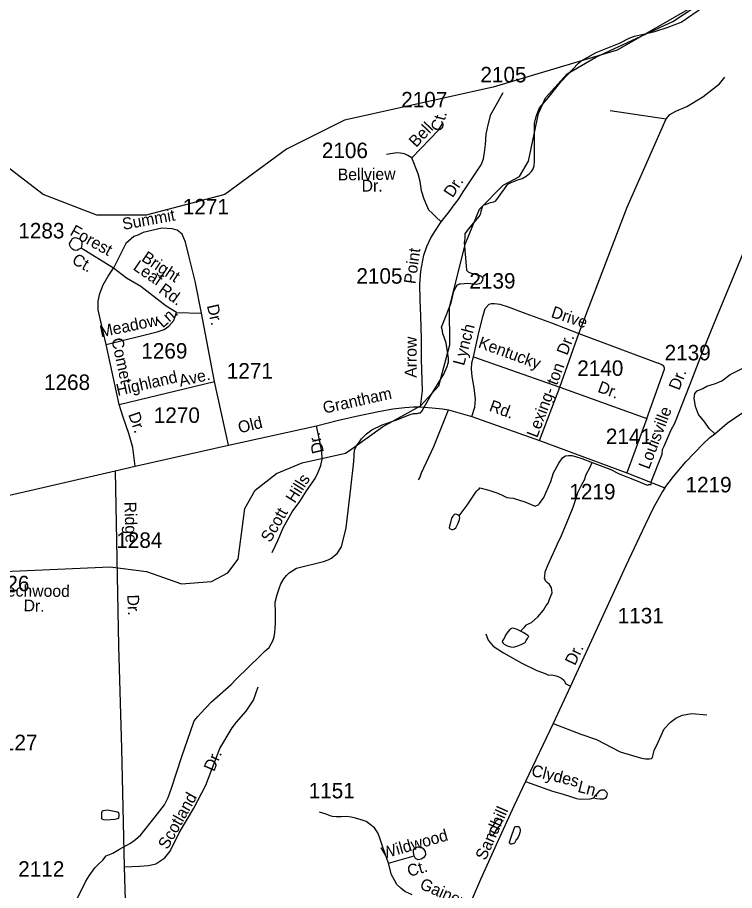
# Model space of a CAD drawing. Extents: x 2260773 to 2342389, y 552869 to 618546.
# Drawn here: x 2278661 to 2284444, y 575188 to 582228 of the extents above; entities that cross this region are included whole.
import ezdxf

# ---------------------------------------------------------------- set-up
doc = ezdxf.new("R2010")
doc.units = 0
for name, color, linetype in [('Exist Boundary Political Urban Extension UEB', 7, 'Continuous'), ('Exist Hydrographic Misc Water Feature', 7, 'Continuous'), ('Exist Road Non-System Type 51', 7, 'Continuous'), ('Exist Road Non-System Type 51 Label', 7, 'Continuous'), ('Exist Road Secondary Type 51 Attributed', 7, 'Continuous'), ('Exist Road Secondary Type 51 Label', 7, 'Continuous'), ('Exist Road Secondary Type 51 Number Label', 7, 'Continuous')]:
    doc.layers.add(name, color=color, linetype=linetype)

msp = doc.modelspace()

# ---------------------------------------------------------------- linework, layer by layer
at = {"layer": 'Exist Boundary Political Urban Extension UEB'}
msp.add_lwpolyline([(2284196, 582364.4), (2283496.6, 581964.8), (2282497.4, 581665.1), (2281298.4, 581398.7), (2280832.1, 581165.6), (2280332.5, 580799.2), (2279699.7, 580632.7), (2279300, 580632.7), (2278867.1, 580799.2), (2278567.3, 581032.4), (2278267.6, 581432), (2278167.6, 581931.5), (2278101, 582497.6)], dxfattribs=at)
at = {"layer": 'Exist Hydrographic Misc Water Feature'}
for points in [[(2278251.7, 577746.1), (2279408.8, 577798.2), (2279700.8, 577759.5), (2279984.8, 577661.9), (2280225.7, 577680), (2280358.8, 577749.4), (2280440.8, 577859.3), (2280494.7, 578268.1), (2280576.8, 578417.3), (2280750.6, 578551.6), (2280957.7, 578635.9), (2281307.8, 578714.1), (2281356.8, 578749.2), (2281604.7, 578927.9), (2281911.9, 579095.5), (2282059.7, 579256.4), (2282148.7, 579589.1), (2282145.8, 579890.9), (2282273.8, 580406.5), (2282387.8, 580682.9), (2282577.9, 580875.8), (2282710.7, 580945.4), (2282783.7, 581068.5), (2282863.7, 581453.9), (2282920.7, 581580.6), (2283093.8, 581773.9), (2283325.7, 581907), (2283947.8, 582196.1), (2284229.8, 582383.8)], [(2281393.5, 578768.1), (2281393.3, 578771.8), (2281413, 578798.1), (2281436.5, 578830.6), (2281476.3, 578870.8), (2281520, 578903.1), (2281601.2, 578944.1), (2281721.2, 578984.8), (2281834.6, 579030.2), (2281848.5, 579032.1), (2281856.3, 579034.2), (2281868.8, 579034.3), (2281884.4, 579034.4), (2281900.4, 579040.5), (2281910.6, 579040.6), (2281924.4, 579056.8), (2281989.4, 579171.5), (2282099.3, 579352.4), (2282126.8, 579414.8), (2282136.6, 579450.6), (2282138.2, 579480.8), (2282119, 579602.5), (2282102.6, 579650.4), (2282090.7, 579678.1), (2282088.2, 579702), (2282080.2, 579730), (2282095.8, 579770.2), (2282157.9, 579926.7), (2282181.3, 580020.5), (2282198.9, 580054.8), (2282210.8, 580070.8), (2282226.6, 580079), (2282234.6, 580081), (2282294.5, 580085.8), (2282362.6, 580076.3), (2282386.6, 580082.5), (2282402.3, 580090.6), (2282408.3, 580102.7), (2282414.2, 580110.7), (2282416.1, 580124.6), (2282406.2, 580138.7), (2282385.9, 580146.6), (2282323.8, 580162.1), (2282299.4, 580173.9), (2282285.7, 580187.7), (2282285.3, 580193.4), (2282283.4, 580225.4), (2282265.8, 580413.4), (2282271.1, 580445.4), (2282270.5, 580483.2), (2282298.8, 580519.5), (2282385.1, 580622.5), (2282399.3, 580646.2), (2282401.3, 580668.3), (2282414.2, 580708.5), (2282422.4, 580716.6), (2282436.8, 580720.5), (2282476.6, 580735.2), (2282502.2, 580741.4), (2282520.2, 580749.3), (2282541.8, 580779.7), (2282616.6, 580882.4), (2282642.9, 580896.7), (2282688.4, 580915), (2282730.4, 580929.3), (2282764.1, 580947.8), (2282791.9, 580969.9), (2282805.7, 580986.1), (2282819.4, 581008), (2282829.3, 581030.4), (2282831.3, 581068.2), (2282830.1, 581372.1), (2282843.6, 581428.1), (2282857.1, 581464.1), (2282870.5, 581498.2), (2282930.4, 581567.1), (2283046.8, 581710.1), (2283185.2, 581859.2), (2283207.4, 581877.4), (2283328.6, 581944.3), (2283515.6, 582020.3), (2283595.3, 582061), (2283637, 582075.5), (2283687, 582087.8), (2283802.4, 582115), (2283900.2, 582145.7), (2284014.1, 582188.5), (2284194.3, 582312.2)], [(2283295.3, 578640.2), (2283446.3, 578583.4), (2283514.3, 578548), (2283650.5, 578493.4), (2283734.8, 578458.4), (2283745, 578456.4), (2283748.7, 578462.4), (2283770.7, 578462.3), (2283772.9, 578482.7), (2283860.5, 578707.1), (2283864.2, 578745.1), (2283876.1, 578771.2), (2283932.6, 578901.8), (2283962.2, 578955.8), (2284087.3, 579271.1), (2284194.5, 579549.8), (2284301.5, 579812.7), (2284421.1, 580099.6), (2284514.8, 580328.4)], [(2279134.8, 575106.7), (2279213.6, 575263.6), (2279238.8, 575307.6), (2279284.5, 575372.1), (2279320, 575406.5), (2279349.7, 575434.5), (2279375.6, 575467.1), (2279429.3, 575489.4), (2279484.9, 575521.9), (2279572, 575570.5), (2279614, 575601), (2279655.9, 575637.3), (2279772.1, 575782.4), (2279847, 575879), (2279876.7, 575937.4), (2279903.8, 576013.6), (2279987.2, 576270.3), (2280080.7, 576540.9), (2280086.5, 576557), (2280101, 576575.1), (2280114.8, 576591.3), (2280136.1, 576615.3), (2280225.5, 576710.1), (2280383.8, 576849.7), (2280421.5, 576889.8), (2280459.5, 576928.3), (2280490.8, 576956.4), (2280534.3, 577000.9), (2280610, 577071.5), (2280659.2, 577120), (2280691.2, 577148.5), (2280707, 577176.5), (2280720.5, 577202.4), (2280732, 577232.7), (2280735.9, 577268.6), (2280741, 577342.9), (2280742.4, 577430.7), (2280739.8, 577514.6), (2280756.8, 577576.5), (2280770.5, 577622.7), (2280784.1, 577660.8), (2280809.5, 577701.2), (2280831.6, 577729.5), (2280853.2, 577749.4), (2280881.1, 577767.9), (2280910.8, 577788.1), (2281128.6, 577840.1), (2281167.7, 577854.4), (2281194, 577868.7), (2281215.7, 577887), (2281239.5, 577904.8), (2281275, 577959.5), (2281311.5, 578111.8), (2281350.2, 578432), (2281372.6, 578648), (2281379.7, 578741.8), (2281391.2, 578760), (2281393.5, 578768.1)], [(2282224.2, 578209.9), (2282287.1, 578294.9), (2282364, 578407.4), (2282371.8, 578415.5), (2282384.1, 578427.5), (2282390, 578435.5), (2282399.9, 578433.6), (2282462, 578416.1), (2282536.4, 578392.8), (2282574.4, 578373.3), (2282608.6, 578357.6), (2282630.6, 578353.9), (2282658.5, 578352.1), (2282753, 578322.8), (2282837.3, 578287.8), (2282847.1, 578294), (2282859, 578295.9), (2282870.7, 578310), (2282906.6, 578356.5), (2282963, 578487.1), (2282984.5, 578557.2), (2283027.8, 578633.4), (2283057.3, 578677.7), (2283067.5, 578685.8), (2283081.3, 578693.9), (2283104.8, 578696), (2283131.1, 578694.6), (2283161.2, 578686.8), (2283213.5, 578671.2), (2283295.3, 578640.2)], [(2282718.7, 577279.3), (2282726.3, 577287.5), (2282750.3, 577311.5), (2282767.7, 577331.9), (2282782.3, 577339.9), (2282805.7, 577350.2), (2282857.8, 577394.6), (2282904.5, 577448.8), (2282924.6, 577485.2), (2282940.2, 577505.1), (2282949.8, 577529.2), (2282965.8, 577569.3), (2282973.4, 577589.7), (2282971.2, 577609.5), (2282967.1, 577629.6), (2282961.1, 577643.5), (2282951.3, 577655.1), (2282933, 577673.2), (2282918.3, 577686.8), (2282918.5, 577692.9), (2282910.7, 577707), (2282914.6, 577720.7), (2282918, 577757), (2282941.6, 577817.1), (2283008.1, 577963.6), (2283025.5, 578001.6), (2283041.1, 578032.1), (2283088.2, 578148.2), (2283143, 578278.7), (2283168, 578352.8), (2283179.7, 578396.9), (2283213.3, 578461.1), (2283235.1, 578499.2), (2283248.4, 578541.8), (2283276.1, 578595.6), (2283295.3, 578640.2)], [(2282224.2, 578209.9), (2282215.7, 578216), (2282204.1, 578219.8), (2282189.9, 578222), (2282182.1, 578217.9), (2282172.3, 578207.6), (2282162, 578189.7), (2282150.9, 578145.5), (2282145, 578125.3), (2282143.2, 578111.4), (2282145, 578107.4), (2282149.5, 578103.5), (2282165.3, 578099.5), (2282173.5, 578099.5), (2282184.8, 578103.9), (2282197.1, 578111.7), (2282214.5, 578150.1), (2282226.4, 578180), (2282228.5, 578192.2), (2282226.2, 578204.3), (2282224.2, 578209.9)], [(2282718.7, 577279.3), (2282690.2, 577292.9), (2282666.7, 577301), (2282656.2, 577304.6), (2282646.6, 577300.8), (2282634.5, 577296.5), (2282615, 577274.3), (2282597.1, 577246.2), (2282585, 577220), (2282573.6, 577203.9), (2282571.5, 577194), (2282577.5, 577183.8), (2282585.5, 577176.1), (2282611.7, 577162.5), (2282639.8, 577152.5), (2282661.5, 577150.9), (2282695.6, 577161.2), (2282723.5, 577173.2), (2282755.2, 577187.8), (2282765.1, 577203.8), (2282775.1, 577219.8), (2282780.9, 577231.9), (2282784.8, 577237.7), (2282776.8, 577245.8), (2282740.5, 577267.5), (2282718.7, 577279.3)], [(2279340.5, 575796.3), (2279340.5, 575818.2), (2279345.8, 575830.4), (2279354.2, 575834.4), (2279386, 575839), (2279468, 575821.7), (2279475.8, 575817.7), (2279478.5, 575799.5), (2279476.5, 575769.8), (2279466.4, 575767.6), (2279446.5, 575761.3), (2279412.7, 575757.1), (2279374.7, 575756.7), (2279356.9, 575758.6), (2279344.8, 575762.5), (2279340.7, 575766.3), (2279340.5, 575772.4), (2279340.7, 575776.5), (2279340.5, 575796.3)], [(2282513.1, 575738.1), (2282478, 575687.8), (2282471.6, 575665.7), (2282470.2, 575653.7), (2282470.2, 575644), (2282473.9, 575637.7), (2282480.1, 575631.9), (2282492.6, 575632.1), (2282505.9, 575646.3), (2282523.5, 575678.5), (2282557.6, 575716.8), (2282559.2, 575726.7), (2282567.2, 575738.9), (2282567.2, 575748.6), (2282567.2, 575758.7), (2282552.8, 575762.5), (2282543.2, 575760.3), (2282531.1, 575756.5), (2282523.1, 575754.4), (2282513.1, 575738.1)], [(2282708.1, 575638.2), (2282700.1, 575618.3), (2282688, 575603.9), (2282684.3, 575600), (2282680.4, 575592), (2282670.8, 575571.6), (2282660.7, 575567.8), (2282652.7, 575565.8), (2282644.7, 575563.4), (2282636.5, 575563.4), (2282636.9, 575567.4), (2282628.5, 575571.5), (2282628.3, 575577.6), (2282645.9, 575627.6), (2282667.5, 575689.7), (2282671.6, 575701.7), (2282681.2, 575705.9), (2282691.5, 575703.9), (2282701.3, 575704.1), (2282709.3, 575693.9), (2282715.5, 575684.1), (2282715.9, 575666.2), (2282713.6, 575656), (2282708.1, 575638.2)]]:
    msp.add_lwpolyline(points, dxfattribs=at)
at = {"layer": 'Exist Road Non-System Type 51'}
for p, q in [((2283440.7, 581477.8), (2283893.2, 581410.1)), ((2283736.9, 578993.8), (2283574.3, 578557.4)), ((2281653.5, 575407.9), (2281860.5, 575469.5))]:
    msp.add_line(p, q, dxfattribs=at)
for points in [[(2283893.2, 581410.1), (2283922.9, 581444.4), (2283970.6, 581470.9), (2284060.1, 581509.6), (2284189.2, 581586.8), (2284322.3, 581692.1), (2284365.8, 581746.4)], [(2283187.9, 579678.6), (2283578, 580697.7), (2283893.2, 581410.1)], [(2279173.6, 580368.3), (2279153.8, 580356.1), (2279139.8, 580350), (2279119.7, 580351.8), (2279105.7, 580359.7), (2279091.5, 580371.6), (2279083.5, 580389.5), (2279081.2, 580405.4), (2279093, 580425.5), (2279104.8, 580445.7), (2279124.7, 580453.9), (2279140.7, 580452), (2279162.9, 580440.3), (2279179, 580418.4), (2279179.2, 580400.4), (2279173.6, 580368.3)], [(2283879, 579399.8), (2283874.2, 579415), (2283868.1, 579419.6), (2283859, 579427.2), (2283828.5, 579439.4)], [(2284285.9, 578871.8), (2284240.7, 578913.4), (2284204.6, 578964), (2284154, 579027.2), (2284128.7, 579090.4), (2284119.7, 579159.1), (2284125.1, 579195.2), (2284144.1, 579216), (2284187.4, 579235.9), (2284221.8, 579254), (2284290.4, 579277.5), (2284342.7, 579299.1), (2284409.6, 579347.9), (2284526.9, 579409.4), (2284590.2, 579418.4)], [(2283736.9, 578993.8), (2283854.3, 579323.5), (2283879.5, 579393.1), (2283879, 579399.8)], [(2281894.7, 578500.8), (2281907.4, 578515.2), (2281920, 578555), (2282019.4, 578768.2), (2282136.7, 579064.5)], [(2280715.5, 577913.5), (2280764.3, 578014.7), (2280804, 578112.3), (2280876.2, 578240.6), (2280937.6, 578323.7), (2280991.8, 578410.4), (2281062.2, 578511.6), (2281087.5, 578560.4), (2281107.4, 578614.6), (2281118.2, 578667), (2281114.6, 578728.5), (2281100.2, 578809.8), (2281073.1, 578934.4)], [(2282437.5, 577257.3), (2282457.4, 577206.7), (2282498.9, 577159.8), (2282580.2, 577105.6), (2282730.1, 577022.4), (2282851.1, 576962.8), (2282916.1, 576937.5), (2282945, 576924.9), (2282970.3, 576926.7), (2283004.6, 576919.5), (2283028.1, 576912.2), (2283049.7, 576901.4), (2283067.8, 576885.1), (2283084, 576856.2), (2283121.1, 576835.4)], [(2279521.8, 575378.5), (2279644.6, 575385.7), (2279718.6, 575389.3), (2279778.2, 575403.8), (2279849.5, 575451.3), (2279893.8, 575505), (2279966.1, 575653.1), (2280083.4, 575851.9), (2280179.2, 576038), (2280253.2, 576229.5), (2280292.9, 576333.4), (2280392.2, 576501.5), (2280428.4, 576544.8), (2280506, 576634.3), (2280563.8, 576723.7), (2280601.7, 576832.1)], [(2282982, 576535.6), (2283205.9, 576448.2), (2283332.2, 576407), (2283521.5, 576307.1), (2283694.2, 576256.7), (2283727.1, 576250.3), (2283745.6, 576249.5), (2283759.2, 576250.3), (2283775.3, 576252.7), (2283782.5, 576260.7), (2283785.6, 576273.5), (2283796.8, 576318.3), (2283828.2, 576385.5), (2283877.4, 576490.8), (2283928.9, 576544.6), (2283971.4, 576578.1), (2284020.7, 576602.8), (2284099, 576616.2), (2284222.1, 576605)], [(2282759.3, 576068.6), (2282976.4, 575990.2), (2283054.8, 575967.8), (2283128.6, 575943.2), (2283168.9, 575929.7), (2283200.3, 575925.3), (2283280.9, 575927.5), (2283310, 575936.5)], [(2283310, 575936.5), (2283331.7, 575930.9), (2283358.2, 575928.2), (2283376.6, 575926.8), (2283390, 575929.1), (2283401.2, 575933.6), (2283408.9, 575939), (2283415.6, 575947), (2283417.4, 575957.8), (2283418.7, 575968.6), (2283414.7, 575978.4), (2283404.8, 575990.6), (2283395, 575996.4), (2283383.7, 575997.3), (2283372.1, 575996.8), (2283362.2, 575993.7), (2283351, 575985.6), (2283333.5, 575968.6), (2283320.1, 575954.7), (2283312.9, 575944.3), (2283310, 575936.5)], [(2281860.5, 575469.5), (2281854.3, 575495.5), (2281856.3, 575515.4), (2281868, 575531.6), (2281891.9, 575539.7), (2281913.9, 575540), (2281934.1, 575528.2), (2281950.2, 575502.3), (2281952.4, 575476.3), (2281938.8, 575454.2), (2281916.8, 575442), (2281892.9, 575435.9), (2281870.9, 575447.5), (2281860.5, 575469.5)]]:
    msp.add_lwpolyline(points, dxfattribs=at)
at = {"layer": 'Exist Road Secondary Type 51 Attributed'}
for p, q in [((2279435.1, 580207.5), (2279173.6, 580368.3)), ((2279944.4, 579849.6), (2280144.8, 579842.4)), ((2280249.6, 579291.3), (2280144.8, 579842.4)), ((2279482.1, 579107), (2279375.1, 579590.9)), ((2282339.1, 579490.7), (2283034.4, 579247.6)), ((2279482.1, 579107), (2280249.6, 579291.3)), ((2280363.4, 578780), (2280249.6, 579291.3)), ((2282870, 578817.6), (2283034.4, 579247.6)), ((2283034.4, 579247.6), (2283736.9, 578993.8)), ((2282324.7, 579010.9), (2282870, 578817.6)), ((2279609.3, 578610.6), (2280363.4, 578780)), ((2279450.1, 578573.1), (2279609.3, 578610.6))]:
    msp.add_line(p, q, dxfattribs=at)
for points in [[(2282079.1, 580579.3), (2282133.2, 580648), (2282158.5, 580682.3), (2282174.8, 580705.8), (2282216.3, 580756.4), (2282261.5, 580829.1), (2282400.5, 581040.1), (2282418.6, 581087.1), (2282427.6, 581139.5), (2282434.8, 581204.5), (2282442, 581287.6), (2282456.5, 581361.7), (2282478.2, 581444.8), (2282525.1, 581526.1), (2282579.3, 581621.9)], [(2281842.5, 581096.1), (2281987, 581247), (2282055.6, 581318.3), (2282093.5, 581381.6)], [(2281842.5, 581096.1), (2281810, 581116), (2281782.9, 581126.8), (2281750.4, 581132.2), (2281721.5, 581135.8), (2281638.4, 581123.2)], [(2282079.1, 580579.3), (2282035.7, 580619.1), (2282003.2, 580651.6), (2281979.7, 580673.3), (2281961.7, 580711.2), (2281941.8, 580763.6), (2281920.1, 580830.5), (2281909.3, 580904.6), (2281893.1, 580967.8), (2281842.5, 581096.1)], [(2281911, 579088), (2281928.8, 579216.8), (2281920.1, 579471.7), (2281918.3, 579639.7), (2281912.9, 579820.4), (2281909.3, 579951.4), (2281907.5, 580077.9), (2281914.7, 580180.9), (2281938.2, 580311), (2281961.7, 580379.7), (2281996, 580450.1), (2282032.1, 580509.8), (2282079.1, 580579.3)], [(2280144.8, 579842.4), (2280094.3, 580102.6), (2280045.5, 580295.9), (2280016.6, 580417), (2279989.5, 580480.2), (2279949.8, 580513.7), (2279908.3, 580522.7), (2279825.2, 580528.1), (2279676.1, 580492.9), (2279632.3, 580472.6), (2279600.9, 580460.4), (2279536.3, 580406.2), (2279435.1, 580207.5)], [(2279375.1, 579590.9), (2279347, 579716.4), (2279311.5, 579870.1), (2279311.5, 579941.3), (2279324.6, 580003.2), (2279352.7, 580072.5), (2279391.5, 580140.6), (2279435.1, 580207.5)], [(2279944.4, 579849.6), (2279861.3, 579901.1), (2279657.2, 580058.3), (2279539.9, 580127), (2279435.1, 580207.5)], [(2283881.3, 578436.3), (2283951.8, 578526.7), (2284051.1, 578645.9), (2284192, 578790.5), (2284244.3, 578841.1), (2284285.9, 578871.8), (2284385.2, 578956.7), (2284502.6, 579038), (2284971.2, 579304.6), (2285376.6, 579527.7), (2285604.4, 579648.1), (2285795, 579754.2), (2286184.7, 579967.7)], [(2282339.1, 579490.7), (2282384.3, 579698.5), (2282416.8, 579824.9), (2282433, 579881), (2282465.5, 579917.1), (2282483.6, 579922.5), (2282507.1, 579922.5), (2282550.4, 579917.1), (2282619, 579893.6), (2282761.7, 579841.2), (2282967.6, 579765.3), (2283187.9, 579678.6)], [(2279375.1, 579590.9), (2279787.5, 579692.6), (2279845.4, 579711), (2279883, 579737.6), (2279920.9, 579784.6), (2279944.4, 579849.6)], [(2283034.4, 579247.6), (2283187.9, 579678.6)], [(2283187.9, 579678.6), (2283828.5, 579439.4)], [(2282324.7, 579010.9), (2282349.9, 579086.8), (2282355.4, 579150.1), (2282344.5, 579241.3), (2282328.3, 579331.7), (2282322.9, 579393.1), (2282326.5, 579441.9), (2282339.1, 579490.7)], [(2279609.3, 578610.6), (2279590.4, 578760.1), (2279559.7, 578873.9), (2279512.8, 579005.8), (2279482.1, 579107)], [(2280363.4, 578780), (2281073.1, 578934.4), (2281250, 578979.6), (2281392.7, 579012.1), (2281571.5, 579051.9), (2281688.9, 579071.8), (2281784.6, 579082.6), (2281855, 579088), (2281911, 579088)], [(2281911, 579088), (2282006.7, 579080.8), (2282088, 579071.8), (2282136.7, 579064.5), (2282324.7, 579010.9)], [(2282870, 578817.6), (2283574.3, 578557.4), (2283881.3, 578436.3)], [(2277796, 578202), (2278067.6, 578263.9), (2278455, 578344.6), (2279450.1, 578573.1)], [(2279450.1, 578573.1), (2279474.9, 577161), (2279500.1, 576334.3), (2279521.8, 575378.5), (2279536.3, 574929.5), (2279545.3, 574624.1), (2279552.5, 574436.2), (2279565.1, 574331.4), (2279579.6, 574269.9), (2279595.8, 574219.3), (2279621.1, 574172.4), (2279660.9, 574105.5), (2279716.8, 574036.8), (2279772.8, 573975.4), (2279845.1, 573903.1), (2279993.1, 573783.9), (2280150.3, 573660.1), (2280269.4, 573571.6), (2280357.9, 573520.1), (2280460.9, 573474.9), (2280563.8, 573438.8), (2280845.5, 573352), (2281096.5, 573279.8)], [(2283881.3, 578436.3), (2283863.3, 578405.6), (2283787.4, 578270.1), (2283722.4, 578138.2), (2283567.1, 577805.7), (2283121.1, 576835.4), (2282982, 576535.6), (2282759.3, 576068.6), (2282663, 575869.3), (2282535.4, 575587.1), (2282394.4, 575278), (2282261.3, 574966.5)], [(2281843.7, 575152.6), (2281785.5, 575181.7), (2281752, 575208.5), (2281720.6, 575237.7), (2281702.7, 575271.3), (2281678.1, 575316.1), (2281653.5, 575407.9), (2281608.7, 575537.8), (2281579.6, 575618.4), (2281568.4, 575654.3), (2281539.3, 575694.6), (2281505.7, 575721.4), (2281472.2, 575743.8), (2281434.1, 575759.5), (2281387.1, 575773), (2281351.3, 575779.7), (2281317.7, 575784.2), (2281272.9, 575781.9), (2281230.4, 575781.9), (2281201.3, 575786.4), (2281183.4, 575790.9), (2281149.8, 575804.3), (2281098.3, 575820)]]:
    msp.add_lwpolyline(points, dxfattribs=at)

# ---------------------------------------------------------------- texts
at = {"layer": 'Exist Road Non-System Type 51 Label'}
for s, rotation, p in [('Dr.', 68.79351, (2283998.1, 579215.5)), ('Louisville', 69.31037, (2283754.9, 578578.9)), ('Dr.', 102.939, (2281133.3, 578723.4)), ('Hills', 57.91801, (2280897.7, 578305.7)), ('Scott', 59.92132, (2280699.7, 577988.4)), ('Dr.', 67.00232, (2280246.3, 576142.2)), ('Clydes', 346.31416, (2282799.6, 576114.1)), ('Ln.', 345.86209, (2283173.9, 575984.9)), ('Scotland', 60.7834, (2279871.4, 575513.5)), ('Wildwood', 16.08978, (2281611.6, 575442.1)), ('Ct.', 16.08978, (2281819.5, 575297.9))]:
    msp.add_text(s, height=95, rotation=rotation, dxfattribs=at).set_placement(p)
at = {"layer": 'Exist Road Secondary Type 51 Label'}
for s, rotation, p in [('Ct.', 74.5227, (2282082.6, 581302.4)), ('Bell', 46.63808, (2281876, 581174.2)), ('Bellview', 0.65399, (2281244.8, 580913.8)), ('Dr.', 0.32595, (2281437.3, 580823.5)), ('Dr.', 56.54048, (2282170.4, 580768.6)), ('Summit', 10.28867, (2279514.7, 580514.4)), ('Forest', 330.82706, (2279077.9, 580478.2)), ('Ct.', 330.82706, (2279092.8, 580248.3)), ('Bright', 326.63365, (2279654.8, 580270.3)), ('Point', 81.91461, (2281870.6, 580074.9)), ('Leaf', 325.61649, (2279586.6, 580199.3)), ('Rd.', 324.41443, (2279792.4, 580014.8)), ('Dr.', 282.73922, (2280188.2, 579904)), ('Drive', 341.6859, (2282958, 579813.2)), ('Ln.', 41.96405, (2279832.9, 579719.3)), ('Meadow', 11.80512, (2279334.7, 579647.6)), ('Lynch', 74.87289, (2282262.1, 579415)), ('Comet', 281.96626, (2279417.9, 579634.5)), ('Arrow', 89.84791, (2281879.9, 579322.5)), ('Kentucky', 339.89524, (2282370.2, 579569.4)), ('Dr.', 69.34452, (2283094.6, 579498)), ('Lexing- ton', 69.34829, (2282852.6, 578833.2)), ('Highland', 12.9187, (2279469.1, 579175.3)), ('Ave.', 12.9187, (2279974.7, 579250.9)), ('Dr.', 339.68388, (2283333.7, 579210.6)), ('Grantham', 12.53317, (2281135.4, 579032.8)), ('Rd.', 340.01591, (2282458.8, 579057.8)), ('Dr.', 289.08348, (2279553.3, 579027.5)), ('Old', 13.62862, (2280452.5, 578874.2)), ('Ridge', 271.76221, (2279523.6, 578322.1)), ('Beechwood', 359.57974, (2278419.4, 577560.4)), ('Dr.', 358.22434, (2278709.3, 577440.4)), ('Dr.', 271.76221, (2279546.7, 577573.1)), ('Dr.', 64.65658, (2283157.5, 576997.1)), ('Sandhill', 65.85779, (2282436.2, 575426)), ('Gainey', 336.30018, (2281897.7, 575207.1))]:
    msp.add_text(s, height=95, rotation=rotation, dxfattribs=at).set_placement(p)
at = {"layer": 'Exist Road Secondary Type 51 Number Label'}
for s, p in [('2105', (2282394.4, 581704.3)), ('2107', (2281756, 581502.4)), ('2106', (2281115.7, 581093.5)), ('1271', (2279994.6, 580639.5)), ('1283', (2278667.8, 580446.1)), ('2105', (2281394.3, 580081.3)), ('2139', (2282305.9, 580041.3)), ('1269', (2279659.7, 579477)), ('2139', (2283880.3, 579462.9)), ('1271', (2280349.3, 579316.2)), ('2140', (2283175.8, 579337.8)), ('1268', (2278875, 579224.2)), ('1270', (2279760.4, 578958.7)), ('2141', (2283406.5, 578787.6)), ('1219', (2284048.9, 578398.5)), ('1219', (2283112.6, 578341.8)), ('1284', (2279457.8, 577951.1)), ('2126', (2278385.7, 577601.2)), ('1131', (2283501.8, 577342.5)), ('2127', (2278450.7, 576319.9)), ('1151', (2281009.7, 575931.7)), ('2112', (2278667.2, 575299.8))]:
    msp.add_text(s, height=125, dxfattribs=at).set_placement(p)

doc.saveas('drawing.dxf')
